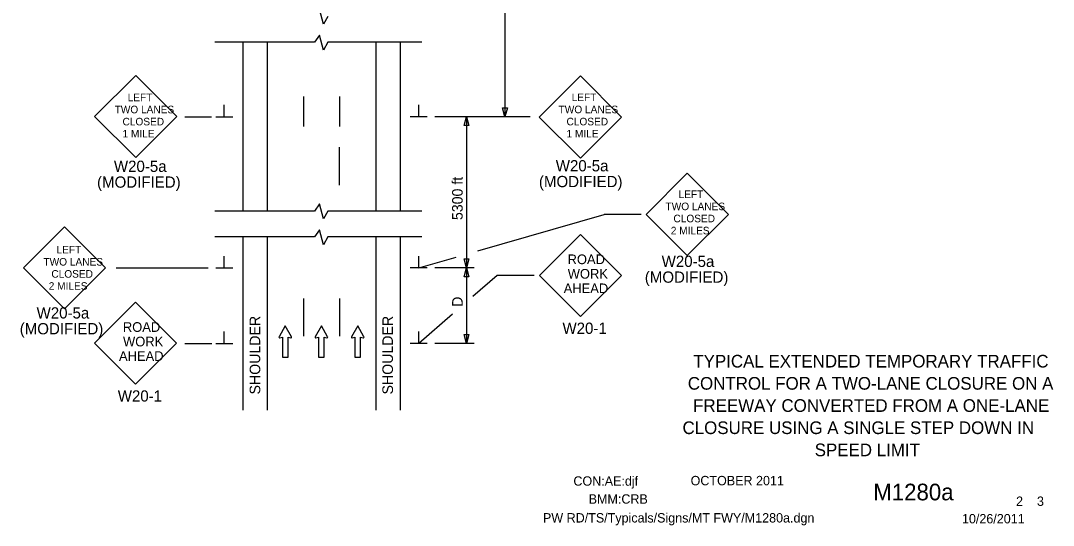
# Model space of a CAD drawing. Extents: x 16590 to 19508, y 5703 to 6974.
# Drawn here: x 17754 to 18437, y 5932 to 6266 of the extents above; entities that cross this region are included whole.
import ezdxf

# ---------------------------------------------------------------- set-up
doc = ezdxf.new("R2010")
doc.units = 0
for name, color, linetype in [('ALI_LEGAL_EX', 7, 'Continuous'), ('BORDER', 7, 'Continuous'), ('BORDER_SIGNAL_WO', 7, 'Continuous'), ('MT_SCRATCH_LEVEL_E', 7, 'Continuous'), ('PAVT_EDGE_EX', 7, 'Continuous'), ('TRAFFIC_SIGNS_PR', 7, 'Continuous'), ('TYPICAL_TEXT_DIMEN_PR', 7, 'Continuous')]:
    doc.layers.add(name, color=color, linetype=linetype)

msp = doc.modelspace()

# ---------------------------------------------------------------- linework, layer by layer
at = {"layer": 'ALI_LEGAL_EX'}
for points in [[(17940.96, 6215.64), (17940.96, 6195.69)], [(17964.96, 6215.64), (17964.96, 6195.69)], [(17964.96, 6156.97), (17964.96, 6181.97)], [(17940.96, 6081.97), (17940.96, 6056.97)], [(17964.96, 6081.97), (17964.96, 6056.97)]]:
    msp.add_lwpolyline(points, dxfattribs=at)
at = {"layer": 'MT_SCRATCH_LEVEL_E'}
for p, q in [((17928.96, 6063.87), (17924.85, 6056.63)), ((17933.1, 6056.63), (17928.96, 6063.87)), ((17952.86, 6063.87), (17948.75, 6056.63)), ((17957.01, 6056.63), (17952.86, 6063.87)), ((17976.91, 6063.87), (17972.8, 6056.63)), ((17981.06, 6056.63), (17976.91, 6063.87)), ((17925.33, 6055.95), (17927.1, 6056.26)), ((17927.1, 6056.26), (17927.1, 6043.01)), ((17930.85, 6043.01), (17930.85, 6056.26)), ((17930.85, 6056.26), (17932.62, 6055.95)), ((17949.23, 6055.95), (17951.01, 6056.26)), ((17951.01, 6056.26), (17951.01, 6043.01)), ((17954.75, 6043.01), (17954.75, 6056.26)), ((17954.75, 6056.26), (17956.53, 6055.95)), ((17973.28, 6055.95), (17975.06, 6056.26)), ((17975.06, 6056.26), (17975.06, 6043.01)), ((17978.8, 6043.01), (17978.8, 6056.26)), ((17978.8, 6056.26), (17980.58, 6055.95)), ((17927.1, 6043.01), (17930.85, 6043.01)), ((17951.01, 6043.01), (17954.75, 6043.01)), ((17975.06, 6043.01), (17978.8, 6043.01))]:
    msp.add_line(p, q, dxfattribs=at)
for centre, start, end in [((17925.25, 6056.41), 150.42484, 279.96381), ((17932.69, 6056.41), 260.03619, 29.77312), ((17949.16, 6056.41), 150.42484, 279.96381), ((17956.6, 6056.41), 260.03619, 29.77312), ((17973.21, 6056.41), 150.42484, 279.96381), ((17980.65, 6056.41), 260.03619, 29.77312)]:
    msp.add_arc(centre, 0.463, start, end, dxfattribs=at)
at = {"layer": 'PAVT_EDGE_EX'}
for p, q in [((17900.96, 6251.44), (17900.96, 6216.94)), ((17916.96, 6251.44), (17916.96, 6216.94)), ((17988.96, 6251.44), (17988.96, 6216.94)), ((18004.96, 6251.44), (18004.96, 6216.94)), ((17900.96, 6216.94), (17900.96, 6139.77)), ((17916.96, 6216.94), (17916.96, 6139.78)), ((17988.96, 6216.94), (17988.96, 6139.78)), ((18004.96, 6216.94), (18004.96, 6139.78)), ((17900.96, 6122.63), (17900.96, 6008.06)), ((17916.96, 6122.63), (17916.96, 6008.06)), ((17988.96, 6122.63), (17988.96, 6008.06)), ((18004.96, 6122.63), (18004.96, 6008.06))]:
    msp.add_line(p, q, dxfattribs=at)
at = {"layer": 'TRAFFIC_SIGNS_PR'}
for p, q in [((17829.94, 6229.48), (17802.75, 6202.29)), ((17857.13, 6202.29), (17829.94, 6229.48)), ((18124.31, 6229.19), (18097.12, 6202)), ((18151.5, 6202), (18124.31, 6229.19)), ((17802.75, 6202.29), (17829.94, 6175.11)), ((17829.94, 6175.11), (17857.13, 6202.29)), ((18097.12, 6202), (18124.31, 6174.82)), ((18124.31, 6174.82), (18151.5, 6202)), ((18195.1, 6164.76), (18167.91, 6137.57)), ((18222.29, 6137.57), (18195.1, 6164.76)), ((18167.91, 6137.57), (18195.1, 6110.38)), ((18195.1, 6110.38), (18222.29, 6137.57)), ((17782.84, 6129.44), (17755.66, 6102.25)), ((17810.03, 6102.25), (17782.84, 6129.44)), ((18124.3, 6124.27), (18097.15, 6097.12)), ((18151.45, 6097.12), (18124.3, 6124.27)), ((17755.66, 6102.25), (17782.84, 6075.06)), ((17782.84, 6075.06), (17810.03, 6102.25)), ((18097.15, 6097.12), (18124.3, 6069.96)), ((18124.3, 6069.96), (18151.45, 6097.12)), ((17829.9, 6079.45), (17802.74, 6052.3)), ((17857.05, 6052.3), (17829.9, 6079.45)), ((17802.74, 6052.3), (17829.9, 6025.15)), ((17829.9, 6025.15), (17857.05, 6052.3))]:
    msp.add_line(p, q, dxfattribs=at)
at = {"layer": 'TYPICAL_TEXT_DIMEN_PR'}
for p, q in [((18074.39, 6555.41), (18074.39, 6202.2)), ((17954.3, 6263.44), (17951.56, 6273.38)), ((17957.05, 6268.58), (17954.3, 6263.44)), ((17951.56, 6256.24), (17948.31, 6251.44)), ((17954.3, 6246.3), (17951.56, 6256.24)), ((17948.31, 6251.44), (17882.36, 6251.44)), ((17957.05, 6251.44), (17954.3, 6246.3)), ((18019.38, 6251.44), (17957.05, 6251.44)), ((17888.58, 6202.2), (17888.58, 6209.99)), ((18017.33, 6202.2), (18017.33, 6209.99)), ((18074.39, 6202.2), (18072.82, 6208.07)), ((18072.82, 6208.07), (18074.39, 6208.07)), ((18074.39, 6208.07), (18075.97, 6208.07)), ((18075.97, 6208.07), (18074.39, 6202.2)), ((17862.57, 6202.2), (17880.11, 6202.2)), ((17882.96, 6202.2), (17894.21, 6202.2)), ((18022.96, 6202.2), (18011.71, 6202.2)), ((18091.13, 6202.2), (18027.96, 6202.2)), ((18047.39, 6196.34), (18048.96, 6202.2)), ((18048.96, 6202.2), (18048.96, 6102.2)), ((18048.96, 6202.2), (18050.53, 6196.34)), ((18048.96, 6196.34), (18047.39, 6196.34)), ((18050.53, 6196.34), (18048.96, 6196.34)), ((17948.31, 6139.77), (17882.36, 6139.77)), ((17951.56, 6144.57), (17948.31, 6139.77)), ((17954.3, 6134.63), (17951.56, 6144.57)), ((17957.05, 6139.77), (17954.3, 6134.63)), ((18019.38, 6139.77), (17957.05, 6139.77)), ((18056.5, 6113.48), (18140.09, 6137.53)), ((18164.57, 6137.53), (18140.09, 6137.53)), ((17951.56, 6127.43), (17948.31, 6122.63)), ((17954.3, 6117.49), (17951.56, 6127.43)), ((17948.31, 6122.63), (17882.36, 6122.63)), ((17957.05, 6122.63), (17954.3, 6117.49)), ((18019.38, 6122.63), (17957.05, 6122.63)), ((17888.58, 6102.2), (17888.58, 6109.99)), ((18017.33, 6102.2), (18017.33, 6109.99)), ((18017.33, 6102.21), (18042.19, 6109.36)), ((18048.96, 6102.2), (18047.39, 6108.07)), ((18047.39, 6108.07), (18048.96, 6108.07)), ((18048.96, 6108.07), (18050.53, 6108.07)), ((18050.53, 6108.07), (18048.96, 6102.2)), ((17817.11, 6102.2), (17877.96, 6102.2)), ((17882.96, 6102.2), (17894.21, 6102.2)), ((18022.96, 6102.2), (18011.71, 6102.2)), ((18053.96, 6102.2), (18027.96, 6102.2)), ((18047.39, 6096.34), (18048.96, 6102.2)), ((18048.96, 6102.2), (18048.96, 6052.2)), ((18048.96, 6102.2), (18050.53, 6096.34)), ((18048.96, 6096.34), (18047.39, 6096.34)), ((18050.53, 6096.34), (18048.96, 6096.34)), ((18069.25, 6097.14), (18053.2, 6083.24)), ((18093.73, 6097.14), (18069.25, 6097.14)), ((18039.57, 6071.45), (18017.33, 6052.21)), ((17888.58, 6052.2), (17888.58, 6059.99)), ((18017.33, 6052.2), (18017.33, 6059.99)), ((18048.96, 6052.2), (18047.39, 6058.07)), ((18047.39, 6058.07), (18048.96, 6058.07)), ((18048.96, 6058.07), (18050.53, 6058.07)), ((18050.53, 6058.07), (18048.96, 6052.2)), ((17862.57, 6052.2), (17880.31, 6052.2)), ((17882.96, 6052.2), (17894.21, 6052.2)), ((18022.96, 6052.2), (18011.71, 6052.2)), ((18053.96, 6052.2), (18027.96, 6052.2))]:
    msp.add_line(p, q, dxfattribs=at)

# ---------------------------------------------------------------- texts
at = {"layer": 'BORDER'}
for s, p in [('TYPICAL EXTENDED TEMPORARY TRAFFIC', (18199.06, 6036.26)), ('CONTROL FOR A TWO-LANE CLOSURE ON A', (18195.43, 6021.59)), ('FREEWAY CONVERTED FROM A ONE-LANE ', (18198.93, 6006.91)), ('CLOSURE USING A SINGLE STEP DOWN IN ', (18191.93, 5992.23)), ('SPEED LIMIT', (18279.43, 5977.56))]:
    msp.add_text(s, height=8.3734, dxfattribs=at).set_placement(p)
at = {"layer": 'BORDER_SIGNAL_WO'}
for s, height, p in [('CON:AE:djf  ', 6.2, (18119.69, 5958.06)), ('    OCTOBER 2011    ', 6.2, (18188.08, 5958.34)), ('    M1280a   ', 11, (18301.86, 5948.38)), ('BMM:CRB   ', 6.2, (18129.81, 5946.17)), (' 2    3 ', 6.2, (18410.45, 5944.7)), ('PW RD/TS/Typicals/Signs/MT FWY/M1280a.dgn      ', 6.2, (18099.55, 5933.71)), ('10/26/2011    ', 6.2, (18376.93, 5933.13))]:
    msp.add_text(s, height=height, dxfattribs=at).set_placement(p)
at = {"layer": 'TRAFFIC_SIGNS_PR'}
for s, height, p in [('LEFT', 5.006, (17824.63, 6212.46)), ('LEFT', 5.006, (18118.55, 6212.5)), ('TWO LANES', 5.006, (17815.98, 6204.46)), ('TWO LANES', 5.006, (18109.9, 6204.49)), ('CLOSED', 5.006, (17821.21, 6196.45)), ('CLOSED', 5.006, (18115.13, 6196.48)), ('1 MILE', 5.006, (17821.2, 6188.44)), ('1 MILE', 5.006, (18115.13, 6188.47)), ('W20-5a', 7.449, (18108.03, 6166.03)), ('W20-5a', 7.449, (17815.51, 6165.67)), ('(MODIFIED)', 7.449, (17804.35, 6155.22)), ('(MODIFIED)', 7.449, (18096.87, 6155.58)), ('LEFT', 5.006, (18189.34, 6148.37)), ('TWO LANES', 5.006, (18180.69, 6140.36)), ('CLOSED', 5.006, (18185.92, 6132.35)), ('2 MILES', 5.006, (18184.17, 6124.34)), ('LEFT', 5.006, (17777.53, 6111.71)), ('TWO LANES', 5.006, (17768.88, 6103.7)), ('ROAD', 6.4, (18115.84, 6104.65)), ('W20-5a', 7.449, (18178.12, 6102.8)), ('CLOSED', 5.006, (17774.11, 6095.69)), ('WORK', 6.4, (18115.95, 6095.05)), ('(MODIFIED)', 7.449, (18166.96, 6092.35)), ('2 MILES', 5.006, (17772.36, 6087.68)), ('AHEAD', 6.4, (18113.26, 6085.45)), ('W20-5a', 7.449, (17764.32, 6068.66)), ('(MODIFIED)', 7.449, (17753.16, 6058.21)), ('ROAD', 6.4, (17821.44, 6059.84)), ('W20-1', 7.44, (18112.47, 6058.52)), ('WORK', 6.4, (17821.55, 6050.24)), ('AHEAD', 6.4, (17818.86, 6040.64)), ('W20-1', 7.44, (17818.07, 6013.71))]:
    msp.add_text(s, height=height, dxfattribs=at).set_placement(p)
at = {"layer": 'TYPICAL_TEXT_DIMEN_PR'}
for s, p in [('5300 ft', (18046.4, 6133.81)), ('D', (18046.4, 6076.42)), ('SHOULDER', (17912.38, 6018.42)), ('SHOULDER', (18000.24, 6018.42))]:
    msp.add_text(s, height=7, rotation=90, dxfattribs=at).set_placement(p)

doc.saveas('drawing.dxf')
